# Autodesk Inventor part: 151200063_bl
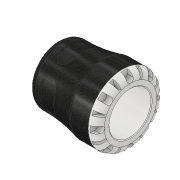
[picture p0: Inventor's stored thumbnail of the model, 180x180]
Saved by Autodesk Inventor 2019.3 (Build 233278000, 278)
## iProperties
Created: 2016-12
Part Number: 151200063_bl
Material: PVC-Piping
Description: PLASSON G-PLASS END CAP 63
Document SubType Name: Modeling
Designer: KIM
Mass: 57.8335 g
Surface Area: 121.129 cm^2
Volume: 41.3096 cm^3
Density: 1.4 g/cm^3
Appearance: Black Cast
Author: KIM
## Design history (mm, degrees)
derived "151200.ipt"
feature "Solid1::151200.ipt" dims "ScaleForDerivedMember" = 10
tag "TaggingFeature1"
body "Solid1"
other parameters: "d0" = 122 [user parameter], "d1" = 39.9 [user parameter], "d2" = 63 [user parameter], "d3" = 78.75 [user parameter], "d4" = 103 [user parameter], "d6" = 95 [user parameter], "d7" = 104.5 [user parameter], "d8" = 87.55 [user parameter], "d13" = 9.7 [user parameter], "d14" = 9.7 [user parameter], "d15" = 0 [user parameter], "d17" = 360 deg [user parameter], "d19" = 8 deg [user parameter], "d20" = 1.26 [user parameter], "d21" = 1.26 [user parameter], "d22" = 8 deg [user parameter], "d24" = 0 [user parameter], "d26" = 360 deg [user parameter], "d32" = 10.3 [user parameter], "d33" = 10.3 [user parameter], "d34" = 13.86 [user parameter], "d35" = 22.05 [user parameter], "d36" = 19.012 [user parameter], "d37" = 0 [user parameter], "d42" = 360 deg [user parameter], "d45" = 18.7425 [user parameter], "d46" = 1.26 [user parameter], "d48" = 0 [user parameter], "d49" = 1.03 [user parameter], "d_" = 63 [user parameter], "E_" = 103 [user parameter], "H_" = 122 [user parameter], "l_" = 95 [user parameter], "d9" = 12.125 [user parameter], "d11" = 103 [user parameter], "d12" = 78.75 [user parameter]
